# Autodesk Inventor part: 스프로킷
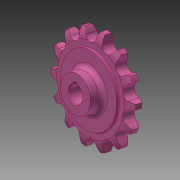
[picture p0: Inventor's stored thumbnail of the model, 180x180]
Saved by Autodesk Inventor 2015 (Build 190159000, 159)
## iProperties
Created: 2016-03
Part Number: 스프로킷
Material: 강철, 탄소
Document SubType Name: Modeling
Designer: mduedu
Density: 7.87 g/cm^3
Mass: 230.696 g
Surface Area: 96.4947 cm^2
Volume: 29.3133 cm^3
Appearance: 분홍색
Author: mduedu
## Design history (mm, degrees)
sketch "스케치1"
  geometry: L1 (0, 5)-(25, 5); L2 (25, 5)-(25, 4.1); L3 (25.5, 3.6)-(29.125, 3.6); L4 (35.5, 2)-(35.5, 0); L5 (35.5, 0)-(0, 0); L6 (0, 0)-(0, 5); L7 (0, -5)-(25, -5); L8 (25, -5)-(25, -4.1); L9 (25.5, -3.6)-(29.125, -3.6); L10 (35.5, -2)-(35.5, 0); L11 (0, 0)-(0, -5); A1 r 13.5 centre (29.125, -9.9) between (35.5, 2) and (29.125, 3.6); A2 r 13.5 centre (29.125, 9.9) between (29.125, -3.6) and (35.5, -2); A3 r 0.5 centre (25.5, 4.1) between (25, 4.1) and (25.5, 3.6); A4 r 0.5 centre (25.5, -4.1) between (25.5, -3.6) and (25, -4.1); 2 further points
  constraints: 22 end point, 8 point on circle, 6 symmetric about line, 5 tangent, 4 centre point, 4 parallel, 4 point on line, 1 equal radius, 1 horizontal, 1 perpendicular, 1 other
  dimensions: "d0" = 71 diameter of L4 L6; "d2" = 50 diameter of L2 L6; "d3" = 1.6 vertical distance of L4.start L3.end; "d4" = 3.6 distance from line of L4.end L3; "d5" = 5 distance between parallel lines of L5 L1; "d6" = 13.5 radius of A1; "d15" = 0.5 radius of A3
revolve "회전1" sketch "스케치1" stored, may be unused: angle "d7" = 90 deg
sketch "스케치2" dims "d8" = 57.16, "d11" = 71
  geometry: L1 (0, 0)-(0, 28.58); A1 r 32.55 centre (0, 0) between (-16.114, 28.281) and (0, 32.55); A2 r 3.97 centre (0, 32.55) between (-3.838, 31.533) and (0, 28.58); A3 r 12.7 centre (-16.114, 28.281) between (-3.838, 31.533) and (-5.392, 35.088); A4 r 12.7 centre (16.114, 28.281) between (5.392, 35.088) and (3.838, 31.533); A5 r 3.97 centre (0, 32.55) between (0, 28.58) and (3.838, 31.533); A6 r 35.5 centre (0, 0) between (5.392, 35.088) and (-5.392, 35.088); 2 further points
  constraints: 12 point on circle, 6 centre point, 4 coincident, 3 symmetric about line, 2 end point, 1 point on line, 1 tangent, 1 vertical, 1 vertical alignment, 7 other
  dimensions: "d10" = 65.1 diameter of A1; "d12" = 12.7 radius of A3
extrude "돌출1" cut sketch "스케치2" stored distance "d13" = 10; taper "d14" = 0 deg
sketch "스케치3"
  geometry: C1 r 11 at (0, 0); 1 further point
  constraints: 1 centre point, 1 coincident
  dimensions: "d19" = 22 diameter of C1
extrude "돌출2" join sketch "스케치3" distance "d20" = 8; taper "d21" = 0 deg
fillet "모깎기1" dims "d22" = 3
sketch "스케치4"
  geometry: L1 (-1.5, 0)-(1.5, 0); L2 (1.5, 0)-(1.5, 6.4); L3 (1.5, 6.4)-(-1.5, 6.4); L4 (-1.5, 6.4)-(-1.5, 0); C1 r 5 at (0, 0); 2 further points
  constraints: 8 end point, 2 coincident, 2 parallel, 1 centre point, 1 horizontal, 1 midpoint, 1 perpendicular
  dimensions: "d23" = 10 diameter of C1; "d25" = 3 distance of L2.end L3.end; "d26" = 6.4 distance of L1.end L2.end
extrude "돌출3" cut sketch "스케치4" stored distance "d27" = 8; taper "d28" = 0 deg
chamfer "모따기1" distance "d29" = 0.5; stored, may be unused: second distance "d30" = 2, angle "d31" = 45 deg
node "솔리드1"
pattern_circular "원형 패턴1" dims angle "d17" = 360 deg
